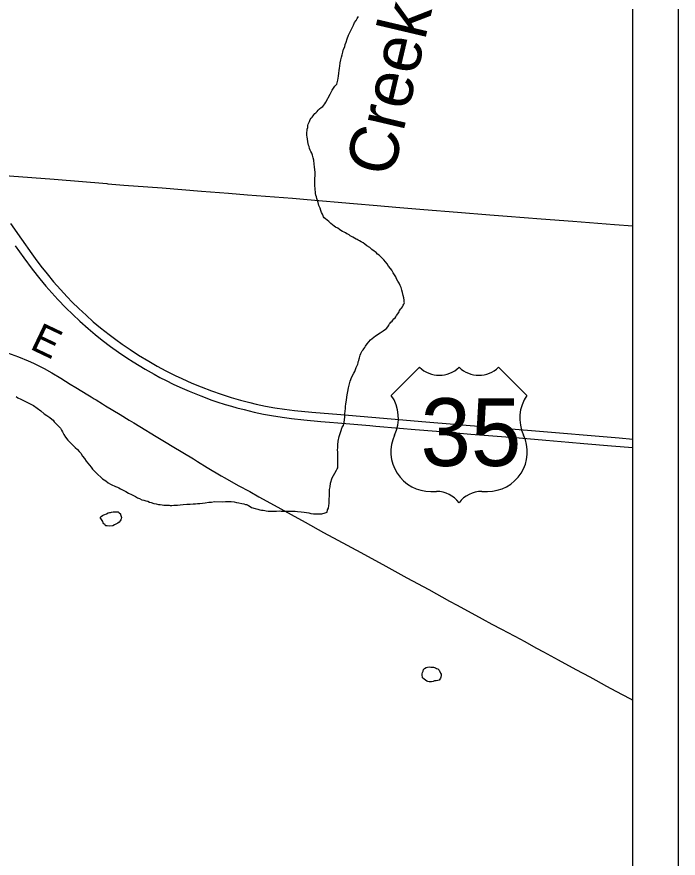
# Model space of a CAD drawing. Extents: x -5.4 to 49.9, y 13.2 to 48.4.
# Drawn here: x 31.879 to 33.165, y 42.099 to 43.736 of the extents above; entities that cross this region are included whole.
import ezdxf

# ---------------------------------------------------------------- set-up
doc = ezdxf.new("R2010")
doc.units = 0
for name, color, linetype in [('GM_X_County_Road', 7, 'Continuous'), ('GM_X_County_Road_Text', 7, 'Continuous'), ('GM_X_Minor_Lake', 7, 'Continuous'), ('GM_X_Minor_River', 7, 'Continuous'), ('GM_X_Minor_River_Text', 7, 'Continuous'), ('GM_X_State_Route', 7, 'Continuous'), ('GM_X_Township', 7, 'Continuous'), ('GM_X_US_Location', 7, 'Continuous'), ('GM_X_US_Route', 7, 'Continuous'), ('GM_X_US_Shield', 7, 'Continuous'), ('SH_Data', 7, 'Continuous')]:
    doc.layers.add(name, color=color, linetype=linetype)

msp = doc.modelspace()

# ---------------------------------------------------------------- linework, layer by layer
at = {"layer": 'GM_X_County_Road'}
msp.add_lwpolyline([(31.8537, 43.0852), (31.8822, 43.0743), (31.9012, 43.0667), (31.9114, 43.0623), (31.9193, 43.0586), (31.9325, 43.0518), (31.9471, 43.0437), (31.9647, 43.0332), (31.9831, 43.0216), (31.9936, 43.015), (32.017, 43.0008), (32.0234, 42.997), (32.0297, 42.993), (32.0334, 42.9908), (32.0454, 42.9831), (32.0518, 42.9792), (32.08, 42.9622), (32.0975, 42.9516), (32.1065, 42.9461), (32.1182, 42.9389), (32.1501, 42.9197), (32.1697, 42.9078), (32.1814, 42.9007), (32.2224, 42.8759), (32.2303, 42.8711), (32.2495, 42.8596), (32.2767, 42.8433), (32.2837, 42.8392), (32.3097, 42.8246), (32.332, 42.8123), (32.3499, 42.8024), (32.3652, 42.794), (32.4399, 42.7531), (32.4757, 42.7332), (32.5035, 42.718), (32.5483, 42.6938), (32.5969, 42.6673), (32.6378, 42.6449), (32.6803, 42.6217), (32.7206, 42.5996), (32.7353, 42.5915), (32.7839, 42.5651), (32.8031, 42.5548), (32.8217, 42.5448), (32.8464, 42.5316), (32.8584, 42.5252), (32.8655, 42.5213), (32.89, 42.5079), (32.9031, 42.5008), (32.9321, 42.4852), (32.9665, 42.4665), (32.9933, 42.4521), (33.0053, 42.4456), (33.0261, 42.4343), (33.0441, 42.4245), (33.0714, 42.4098), (33.0771, 42.4067)], dxfattribs=at)
at = {"layer": 'GM_X_Minor_Lake'}
for points in [[(32.0414, 42.7619), (32.0429, 42.7642), (32.0456, 42.7657), (32.0483, 42.7672), (32.0505, 42.7679), (32.0532, 42.7694), (32.057, 42.7709), (32.0593, 42.7716), (32.0612, 42.772), (32.0631, 42.7723), (32.0662, 42.7731), (32.0688, 42.7734), (32.0711, 42.7734), (32.0734, 42.7734), (32.076, 42.773), (32.0783, 42.7714), (32.0805, 42.7695), (32.0809, 42.7676), (32.0824, 42.7622), (32.0819, 42.7596), (32.0812, 42.7577), (32.08, 42.7554), (32.0781, 42.7532), (32.0758, 42.7513), (32.0693, 42.7476), (32.0655, 42.7461), (32.0602, 42.7454), (32.0549, 42.7458), (32.0518, 42.7459), (32.0507, 42.7482), (32.0485, 42.7497), (32.0473, 42.752), (32.0462, 42.7543), (32.0414, 42.7619)], [(32.6673, 42.4566), (32.6673, 42.4577), (32.6681, 42.4608), (32.6692, 42.4634), (32.67, 42.4665), (32.6719, 42.4683), (32.675, 42.4702), (32.678, 42.4709), (32.6811, 42.4713), (32.6841, 42.4709), (32.6875, 42.4708), (32.6894, 42.4708), (32.6913, 42.47), (32.6932, 42.4696), (32.6955, 42.4684), (32.6981, 42.4677), (32.7004, 42.465), (32.7033, 42.4596), (32.7041, 42.4573), (32.7044, 42.4547), (32.7036, 42.4516), (32.7029, 42.4497), (32.7017, 42.4479), (32.7002, 42.446), (32.6979, 42.4452), (32.6948, 42.4445), (32.6914, 42.4442), (32.6888, 42.4434), (32.6857, 42.4427), (32.6834, 42.4424), (32.6808, 42.4424), (32.6785, 42.4432), (32.6766, 42.444), (32.6713, 42.4474), (32.6683, 42.4501), (32.6673, 42.4566)]]:
    msp.add_lwpolyline(points, dxfattribs=at)
at = {"layer": 'GM_X_Minor_River'}
for points in [[(32.4553, 43.543), (32.4568, 43.5453), (32.4587, 43.5476), (32.4607, 43.5494), (32.463, 43.5517), (32.4653, 43.554), (32.4679, 43.5566), (32.471, 43.5596), (32.4741, 43.5615), (32.476, 43.5637), (32.4779, 43.5663), (32.4802, 43.5697), (32.4887, 43.5852), (32.4926, 43.5932), (32.4973, 43.6007), (32.5015, 43.6048), (32.5031, 43.6124), (32.5047, 43.6204), (32.5055, 43.6265), (32.5059, 43.6314), (32.5067, 43.6359), (32.5072, 43.6401), (32.508, 43.6466), (32.5092, 43.6519), (32.5104, 43.6572), (32.5116, 43.6621), (32.5128, 43.667), (32.5147, 43.6731), (32.5167, 43.6776), (32.5178, 43.6818), (32.5194, 43.6867), (32.5214, 43.6932), (32.5241, 43.7), (32.5272, 43.7068), (32.5311, 43.7143), (32.5338, 43.7196), (32.5361, 43.7245), (32.5388, 43.7287), (32.5411, 43.7324), (32.5438, 43.7366)], [(32.6244, 43.2132), (32.6226, 43.2178), (32.6204, 43.222), (32.6177, 43.2262), (32.6159, 43.2304), (32.6137, 43.2339), (32.6122, 43.2361), (32.611, 43.2381), (32.6095, 43.2404), (32.6081, 43.243), (32.6058, 43.2461), (32.6021, 43.2511), (32.5995, 43.2557), (32.5961, 43.2595), (32.5927, 43.2633), (32.5841, 43.2722), (32.5807, 43.2745), (32.5777, 43.2772), (32.5739, 43.2799), (32.5698, 43.2834), (32.5656, 43.2872), (32.56, 43.2907), (32.5562, 43.2934), (32.5525, 43.2961), (32.5487, 43.2984), (32.5457, 43.3004), (32.5427, 43.3015), (32.5408, 43.3027), (32.5389, 43.3035), (32.5359, 43.3054), (32.5325, 43.3073), (32.5298, 43.3089), (32.5272, 43.3101), (32.5253, 43.3116), (32.523, 43.3128), (32.5208, 43.3139), (32.5181, 43.3155), (32.5155, 43.317), (32.5125, 43.3186), (32.5095, 43.3205), (32.5064, 43.3225), (32.5031, 43.3248), (32.4989, 43.3267), (32.4963, 43.3287), (32.4933, 43.3313), (32.4899, 43.334), (32.4861, 43.3375), (32.4824, 43.3406), (32.4793, 43.3429), (32.4771, 43.3452), (32.4756, 43.3471), (32.4749, 43.349), (32.4737, 43.3517), (32.4719, 43.3555), (32.4704, 43.359), (32.4689, 43.3635), (32.4667, 43.3689), (32.4653, 43.3746), (32.4638, 43.3788), (32.4623, 43.3822), (32.4616, 43.3857), (32.4609, 43.3891), (32.4601, 43.3925), (32.4591, 43.4024), (32.4588, 43.4062), (32.4588, 43.4093), (32.4588, 43.4127), (32.4589, 43.4165), (32.4589, 43.4214), (32.459, 43.4275), (32.4591, 43.4336), (32.4584, 43.4385), (32.458, 43.4438), (32.4573, 43.4495), (32.4566, 43.4568), (32.4552, 43.4617), (32.4541, 43.4667), (32.4526, 43.4705), (32.4508, 43.4736), (32.4496, 43.4766), (32.4485, 43.48), (32.4474, 43.4835), (32.4463, 43.4865), (32.4456, 43.4896), (32.4449, 43.493), (32.4442, 43.4983), (32.4435, 43.5021), (32.4431, 43.5056), (32.4432, 43.5086), (32.4432, 43.5113), (32.4436, 43.5139), (32.444, 43.5173), (32.4448, 43.5207), (32.4452, 43.5242), (32.446, 43.5268), (32.4468, 43.5295), (32.448, 43.5325), (32.4499, 43.5363), (32.4518, 43.5389), (32.4534, 43.5408), (32.4553, 43.543)], [(32.4805, 42.7718), (32.4824, 42.7725), (32.4836, 42.7771), (32.4851, 42.7805), (32.486, 42.7854), (32.4864, 42.7892), (32.4868, 42.793), (32.4868, 42.7976), (32.4869, 42.804), (32.4874, 42.8101), (32.4874, 42.8162), (32.4882, 42.8215), (32.4891, 42.8287), (32.4926, 42.8393), (32.4973, 42.8484), (32.5007, 42.854), (32.5019, 42.857), (32.5031, 42.8589), (32.5031, 42.8612), (32.5035, 42.8662), (32.5032, 42.8726), (32.5037, 42.8802), (32.5037, 42.8859), (32.5034, 42.8897), (32.503, 42.8928), (32.5031, 42.8981), (32.5031, 42.9034), (32.504, 42.9102), (32.506, 42.9197), (32.5091, 42.9292), (32.5119, 42.9375), (32.5142, 42.9413), (32.515, 42.9443), (32.5158, 42.9469), (32.517, 42.9579), (32.5171, 42.9636), (32.5179, 42.969), (32.5183, 42.9739), (32.5184, 42.9781), (32.5192, 42.9834), (32.52, 42.9902), (32.5208, 42.9959), (32.5216, 43.0008), (32.5228, 43.0073), (32.5244, 43.0145), (32.5256, 43.0194), (32.5272, 43.027), (32.5307, 43.0357), (32.5342, 43.0429), (32.5365, 43.0459), (32.5393, 43.0538), (32.5412, 43.0576), (32.5424, 43.0606), (32.5428, 43.0629), (32.5432, 43.0648), (32.544, 43.0671), (32.5451, 43.0705), (32.5455, 43.0728), (32.5463, 43.0754), (32.5471, 43.0777), (32.5483, 43.0807), (32.5494, 43.0834), (32.551, 43.086), (32.5525, 43.0879), (32.5541, 43.0901), (32.5556, 43.0924), (32.5575, 43.095), (32.5602, 43.0996), (32.5672, 43.1075), (32.5767, 43.1157), (32.5855, 43.1213), (32.5916, 43.1254), (32.5958, 43.1284), (32.5981, 43.1299), (32.6024, 43.1356), (32.6035, 43.1378), (32.6051, 43.1397), (32.6066, 43.142), (32.6089, 43.1439), (32.6104, 43.1457), (32.6124, 43.1484), (32.6147, 43.1502), (32.6162, 43.1521), (32.6177, 43.1552), (32.6204, 43.1582), (32.6224, 43.1623), (32.6235, 43.1646), (32.6258, 43.1676), (32.627, 43.1695), (32.6289, 43.1721), (32.6305, 43.1748), (32.6316, 43.1767), (32.6328, 43.1797), (32.6324, 43.1816), (32.6325, 43.185), (32.6318, 43.1896), (32.6307, 43.1941), (32.6292, 43.1995), (32.6281, 43.204), (32.6263, 43.2094), (32.6244, 43.2132)], [(31.8777, 42.9975), (31.8811, 42.9948), (31.8867, 42.9924), (31.892, 42.9897), (31.9116, 42.9796), (31.9188, 42.9746), (31.9256, 42.9692), (31.9323, 42.9638), (31.9376, 42.9603), (31.9414, 42.958), (31.9436, 42.9564), (31.9474, 42.9534), (31.95, 42.9514), (31.9519, 42.948), (31.956, 42.9434), (31.9602, 42.9395), (31.9624, 42.9376), (31.9639, 42.9357), (31.9658, 42.9319), (31.968, 42.9284), (31.9706, 42.9238), (31.9736, 42.9185), (31.9785, 42.9124), (31.9837, 42.907), (31.9886, 42.9024), (31.9927, 42.8985), (31.9969, 42.8943), (32.0006, 42.8905), (32.0036, 42.887), (32.0066, 42.8816), (32.0107, 42.877), (32.0141, 42.8717), (32.0174, 42.8675), (32.0204, 42.8636), (32.0234, 42.8598), (32.0264, 42.856), (32.0294, 42.8525), (32.0332, 42.8487), (32.0456, 42.8375), (32.052, 42.8333), (32.0565, 42.8298), (32.061, 42.8271)], [(32.061, 42.8271), (32.0652, 42.8251), (32.0682, 42.8236), (32.0712, 42.8224), (32.0746, 42.8208), (32.0773, 42.8197), (32.0807, 42.8177), (32.086, 42.8154), (32.0912, 42.8123), (32.0961, 42.8092), (32.1022, 42.8069), (32.106, 42.8049), (32.1097, 42.8026), (32.1135, 42.8003), (32.1177, 42.7987), (32.1222, 42.7967), (32.1263, 42.7956), (32.1301, 42.7944), (32.1339, 42.7936), (32.1369, 42.792), (32.1403, 42.7912), (32.1453, 42.7896), (32.1498, 42.7885), (32.1543, 42.7876), (32.1581, 42.7872), (32.1619, 42.7864), (32.1653, 42.786), (32.1684, 42.786), (32.1718, 42.7859), (32.1752, 42.7859), (32.1775, 42.7855), (32.1805, 42.7855), (32.1847, 42.7858), (32.1915, 42.7861), (32.1968, 42.7864), (32.2029, 42.7871), (32.2097, 42.7878), (32.2162, 42.7877), (32.2219, 42.7884), (32.2265, 42.7887), (32.2306, 42.7891), (32.2348, 42.7894), (32.2401, 42.7901), (32.2454, 42.7908), (32.2527, 42.7919), (32.258, 42.7922), (32.2633, 42.7929), (32.2785, 42.7927), (32.2846, 42.793), (32.2902, 42.7929), (32.2959, 42.7929), (32.3016, 42.7924), (32.3062, 42.7912), (32.3111, 42.7904), (32.3168, 42.7892), (32.3206, 42.7888), (32.3236, 42.7876), (32.3255, 42.7872), (32.3274, 42.7868), (32.3296, 42.7853), (32.3326, 42.7834), (32.3357, 42.7818), (32.3425, 42.7798), (32.3478, 42.7782), (32.3519, 42.7771), (32.355, 42.7766), (32.3584, 42.7762), (32.3614, 42.7754), (32.364, 42.775), (32.3682, 42.7746), (32.3728, 42.7745), (32.3766, 42.7741), (32.38, 42.7745), (32.3838, 42.7744), (32.3891, 42.7747), (32.3933, 42.7743), (32.3986, 42.7746), (32.4031, 42.7746), (32.4073, 42.7745), (32.4103, 42.7745), (32.413, 42.7745), (32.4153, 42.7744), (32.4172, 42.7744), (32.4206, 42.7744), (32.4251, 42.7739), (32.4323, 42.7731), (32.4376, 42.7723), (32.4426, 42.7715), (32.4467, 42.771), (32.449, 42.7703), (32.4509, 42.7699), (32.4562, 42.7694), (32.4581, 42.7694), (32.4607, 42.7694), (32.4642, 42.7693), (32.4683, 42.7693), (32.4702, 42.7689), (32.4721, 42.7692), (32.474, 42.7696), (32.4771, 42.7707), (32.4805, 42.7718)]]:
    msp.add_lwpolyline(points, dxfattribs=at)
at = {"layer": 'GM_X_State_Route'}
for points in [[(31.7644, 43.4345), (31.777, 43.4335), (31.7917, 43.4324), (31.7981, 43.4318), (31.832, 43.4291), (31.8648, 43.4267), (31.9515, 43.4199), (32.0544, 43.4114)], [(32.0544, 43.4114), (32.0561, 43.4112), (32.0871, 43.4087), (32.1336, 43.4052), (32.1615, 43.4031), (32.2383, 43.3968), (32.2909, 43.3928), (32.3275, 43.3899), (32.4155, 43.3831), (32.4439, 43.3804), (32.5337, 43.3729), (32.5801, 43.3687), (32.616, 43.3655), (32.6705, 43.3613), (32.7362, 43.3561), (32.7993, 43.3508), (32.8328, 43.3484), (32.899, 43.3431), (32.9603, 43.3384), (33.0415, 43.332), (33.0771, 43.3294)]]:
    msp.add_lwpolyline(points, dxfattribs=at)
at = {"layer": 'GM_X_Township'}
msp.add_lwpolyline([(31.4373, 40.6437), (33.0771, 40.6437), (33.0771, 44.431)], dxfattribs=at)
at = {"layer": 'GM_X_US_Route'}
for points in [[(31.8668, 43.3339), (31.8881, 43.3033), (31.9081, 43.2749), (31.9147, 43.2658), (31.9259, 43.2509), (31.9379, 43.2358), (31.9506, 43.2205), (31.9638, 43.2055), (31.9769, 43.1914), (31.9869, 43.1811), (31.9997, 43.1685), (32.0138, 43.1553), (32.0278, 43.1429), (32.0421, 43.1309), (32.0586, 43.1177), (32.0716, 43.1081), (32.0838, 43.0995), (32.0998, 43.0887), (32.1159, 43.0781), (32.1355, 43.066), (32.1522, 43.0564), (32.1686, 43.0475), (32.1869, 43.0382), (32.1999, 43.0321), (32.2192, 43.0235), (32.2376, 43.016), (32.258, 43.0083), (32.2768, 43.0017), (32.2958, 42.9957), (32.3143, 42.9904), (32.3324, 42.9856), (32.3445, 42.9828), (32.3628, 42.9789), (32.3811, 42.9755), (32.3996, 42.9727), (32.4193, 42.9703), (32.4528, 42.9671), (32.5091, 42.9622), (32.6069, 42.9539), (32.6744, 42.9483), (32.7927, 42.9385), (32.88, 42.9311), (33.0503, 42.9168), (33.0771, 42.9144)], [(31.8761, 43.2903), (31.8927, 43.2671), (31.909, 43.2452), (31.924, 43.2262), (31.9358, 43.2118), (31.9472, 43.1987), (31.959, 43.186), (31.9746, 43.1699), (31.9878, 43.1568), (32.0019, 43.1437), (32.0176, 43.1296), (32.0313, 43.118), (32.0449, 43.1071), (32.0613, 43.0948), (32.0769, 43.0836), (32.0928, 43.0727), (32.1053, 43.0646), (32.1286, 43.0505), (32.1459, 43.0408), (32.1574, 43.0346), (32.1695, 43.0283), (32.1834, 43.0214), (32.1964, 43.0155), (32.2141, 43.008), (32.2371, 42.9986), (32.2586, 42.9904), (32.2679, 42.9872), (32.2845, 42.9819), (32.2964, 42.9783), (32.3072, 42.9754), (32.321, 42.9718), (32.3409, 42.967), (32.3591, 42.9632), (32.3743, 42.9603), (32.3952, 42.957), (32.4136, 42.9544), (32.437, 42.9517), (32.4705, 42.949), (32.4874, 42.9477)], [(32.4874, 42.9477), (32.5033, 42.9464), (32.5658, 42.9409), (32.5776, 42.9398), (32.6234, 42.9359), (32.6537, 42.9335), (32.6952, 42.9301), (32.7193, 42.928), (32.7621, 42.9243), (32.8562, 42.9167), (32.9082, 42.9124), (32.9528, 42.9085), (32.9818, 42.906), (33.0357, 42.9015), (33.0771, 42.898)]]:
    msp.add_lwpolyline(points, dxfattribs=at)
at = {"layer": 'GM_X_US_Shield'}
for p, q in [((32.6623, 43.0545), (32.6074, 42.9996)), ((32.8711, 42.9996), (32.8161, 43.0545)), ((32.6843, 42.8128), (32.6953, 42.8128)), ((32.7832, 42.8128), (32.7942, 42.8128))]:
    msp.add_line(p, q, dxfattribs=at)
for centre, radius, start, end in [((32.7008, 43.0937), 0.0549, 225.573, 314.427), ((32.7777, 43.0937), 0.0549, 225.573, 314.427), ((32.5444, 42.9554), 0.0769, 334.5471, 35.0009), ((32.9341, 42.9554), 0.0769, 144.9991, 205.4529), ((32.6835, 42.8897), 0.0769, 154.8319, 270.6383), ((32.795, 42.8897), 0.0769, 269.3617, 25.1681), ((32.6953, 42.7579), 0.0549, 36.8699, 90), ((32.7832, 42.7579), 0.0549, 90, 143.1301)]:
    msp.add_arc(centre, radius, start, end, dxfattribs=at)
at = {"layer": 'SH_Data'}
msp.add_line((33.1653, 47.5483), (33.1653, 40.5483), dxfattribs=at)

# ---------------------------------------------------------------- texts
at = {"layer": 'GM_X_County_Road_Text'}
msp.add_text('E', height=0.0568, rotation=334.5753, dxfattribs=at).set_placement((31.9025, 43.0909))
at = {"layer": 'GM_X_Minor_River_Text'}
msp.add_text('Creek', height=0.09469, rotation=76.7336, dxfattribs=at).set_placement((32.6097, 43.4217))
at = {"layer": 'GM_X_US_Location'}
for s in ['0', '/']:
    msp.add_text(s, height=0.000189, dxfattribs=at).set_placement((32.7392, 42.9271))
msp.add_text('35', height=0.000189, rotation=0, dxfattribs=at).set_placement((32.7001, 42.8879))
at = {"layer": 'GM_X_US_Shield'}
msp.add_text('35', height=0.13184, dxfattribs=at).set_placement((32.6642, 42.8622))

doc.saveas('drawing.dxf')
